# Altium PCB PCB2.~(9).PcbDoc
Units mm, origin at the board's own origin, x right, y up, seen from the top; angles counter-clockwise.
Board outline 79 x 39 mm, 2 copper layers (Top Layer, Bottom Layer); 4 components, 3 nets, 8 pads, 0 vias.
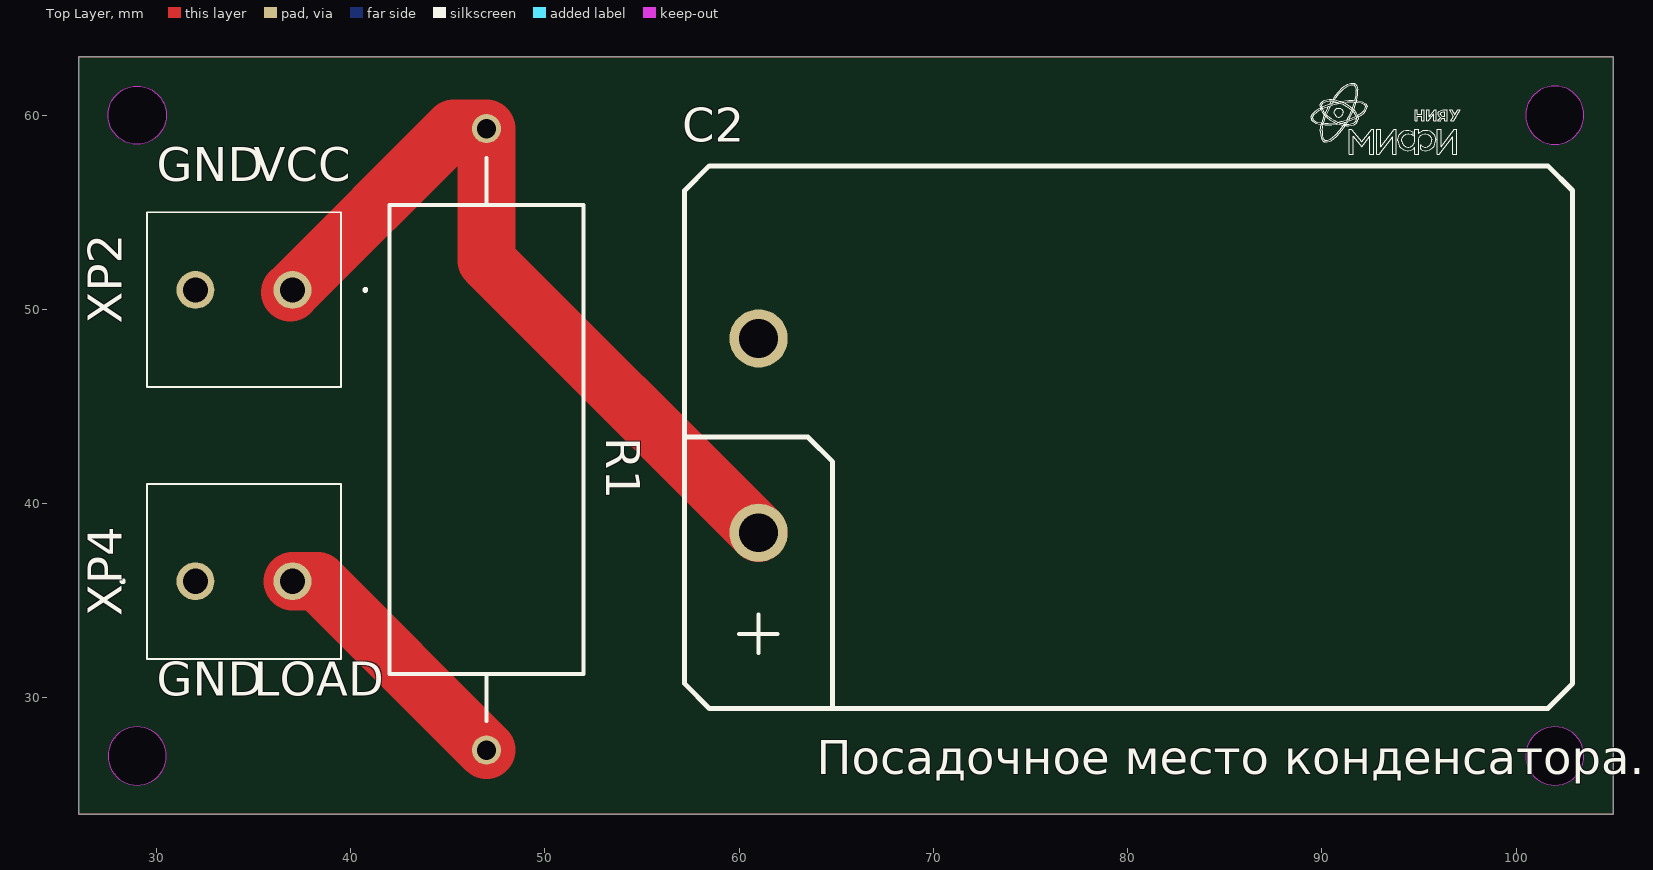
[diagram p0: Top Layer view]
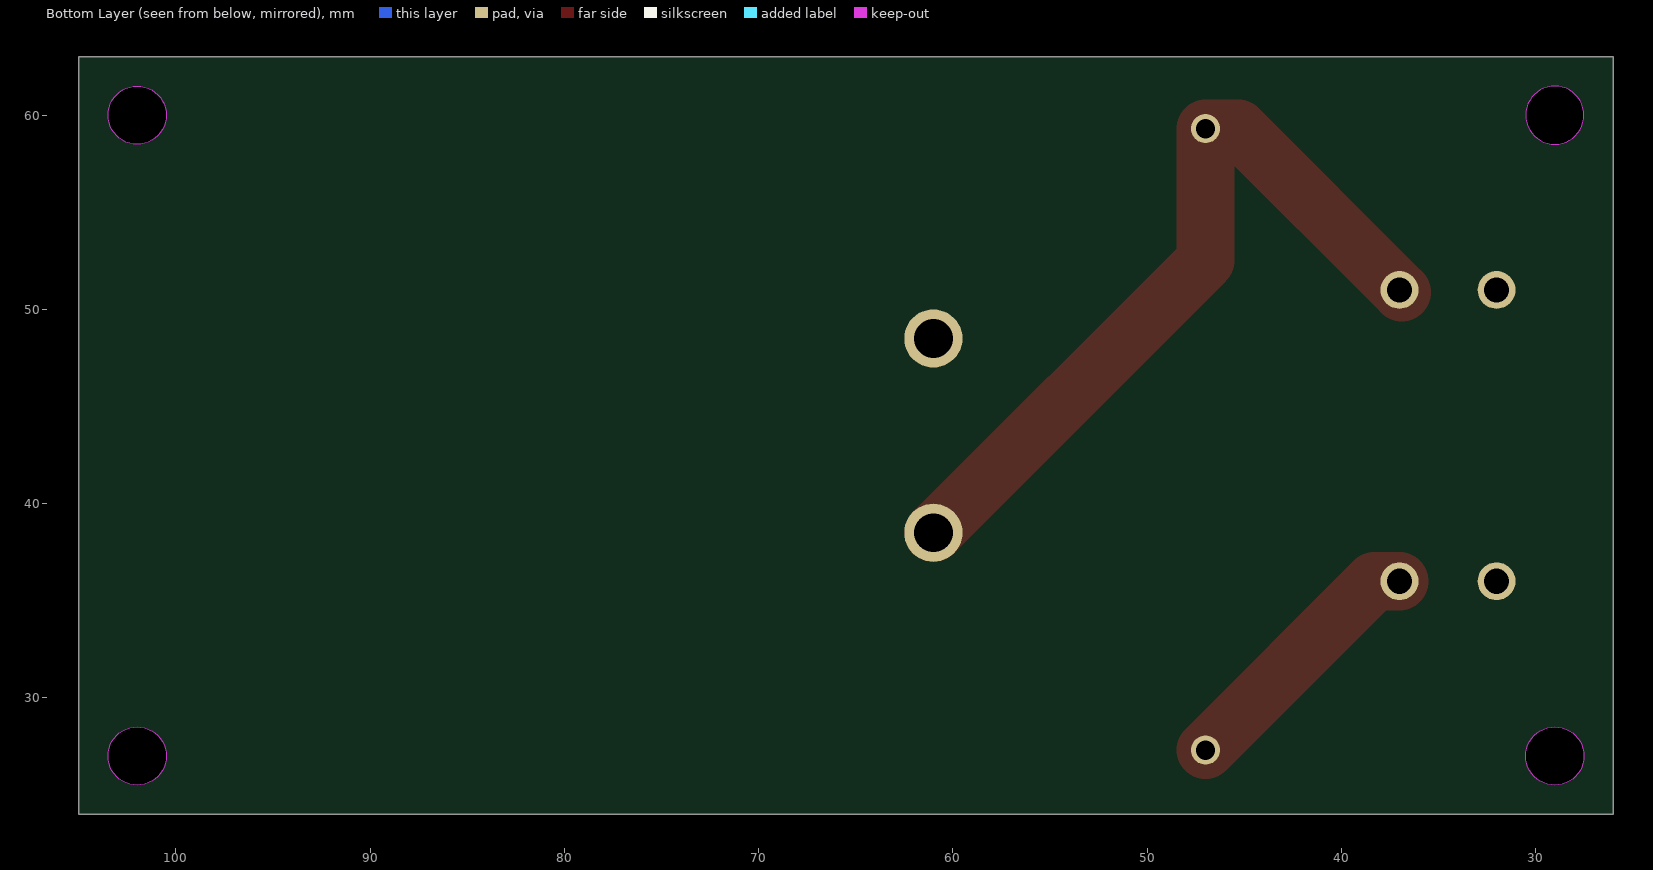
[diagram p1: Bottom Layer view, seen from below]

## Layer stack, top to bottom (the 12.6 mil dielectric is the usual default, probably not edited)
Top Solder: solder mask 0.0102, Solder Resist, Dk 3.5
Top Layer: signal copper 0.0356
Dielectric 1: dielectric 0.32, FR-4, Dk 4.8
Bottom Layer: signal copper 0.0356
Bottom Solder: solder mask 0.0102, Solder Resist, Dk 3.5

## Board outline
26,24 105,24 105,63 26,63
cut-out: 100.5,60 ccw(c102,60) 102,58.5 ccw(c102,60) 103.5,60 ccw(c102,60) 102,61.5 ccw(c102,60)
cut-out: 100.5,27 ccw(c102,27) 102,25.5 ccw(c102,27) 103.5,27 ccw(c102,27) 102,28.5 ccw(c102,27)
cut-out: 27.5,27 ccw(c29,27) 29,25.5 ccw(c29,27) 30.5,27 ccw(c29,27) 29,28.5 ccw(c29,27)
cut-out: 29,58.5 cw(c29,60) 27.5,60 cw(c29,60) 29,61.5 cw(c29,60) 30.5,60 cw(c29,60)

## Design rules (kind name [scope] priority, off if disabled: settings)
Clearance [All] p1: gap=0.254 ignorepadtopadclearanceinfootprint=FALSE except(0: Arc-Hole Track-Hole SMDPad-Hole THPad-Hole Via-Hole Fill-Hole Poly-Hole Region-Hole Text-Hole)
PlaneConnect [All] p1: planeconnectstyle=Relief reliefexpansion=1 reliefentries=4 reliefconductorwidth=3 reliefairgap=0.5
PolygonConnect [All] p1: connectstyle=Relief reliefconductorwidth=1 reliefentries=4 polygonreliefangle="90 Angle" airgapwidth=0.5
RoutingVias [All] p1: holewidth=0.711 width=1.27 viastyle="Through Hole" minholewidth=0.711 minwidth=1.27 maxholewidth=0.711 maxwidth=1.27
SolderMaskExpansion [All] p1: expansion=0.102 istentingtop=FALSE
Width [All] p1: maxlimit=20 minlimit=1 preferedwidth=8
29 further rules are at their usual default settings.

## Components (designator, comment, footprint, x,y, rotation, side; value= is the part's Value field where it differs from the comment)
C2 "1500uF" K50-98-63V-1500uF 61,48.5 r270 top
R1 "2 Ом" "SQP 5W2" 46.99,59.305 r270 top
XP2 "DG300-5.0-02P-12-00A_H_" DG3005002P1200AH 37,51 r180 top
XP4 "DG300-5.0-02P-12-00A_H_" DG3005002P1200AH 32,36 r0 top

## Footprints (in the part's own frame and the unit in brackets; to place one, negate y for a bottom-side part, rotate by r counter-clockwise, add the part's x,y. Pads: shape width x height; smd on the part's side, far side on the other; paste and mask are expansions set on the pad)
DG3005002P1200AH [mm]
  round 1.95 hole 1.3: 1(0,0) 2(5,0)
  silkscreen extent -3.8,-4 7.5,5, body extent -2.46,-4 7.54,5, height 12.6
K50-98-63V-1500uF [mm]
  round 3 hole 2: 1(0,0) 2(10,0)
  silkscreen extent -8.89,-3.81 19.05,41.91, body extent -7.5,10 17.5,40, height 25
"SQP 5W2" [mm]
  round 1.5 hole 1: 1(0,0) 2(32,0)
  silkscreen extent 1.5,-5 30.5,5, body extent -0.35,-5 32.35,5, height 9

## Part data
C2: library part K50-98-63V-1500uF
R1: library part "SQP 5W"
XP2 XP4: "Клеммник винтовой, 2-контактный, 5мм, прямой", Manufacturer_Name=Degson, Manufacturer_Part_Number=DG300-5.0-02P-12-00A(H)

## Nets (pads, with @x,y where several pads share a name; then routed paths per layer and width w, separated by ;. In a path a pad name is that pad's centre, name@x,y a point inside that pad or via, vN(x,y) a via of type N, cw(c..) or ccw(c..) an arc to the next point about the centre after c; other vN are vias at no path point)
GND: C2.1 XP2.2 XP4.1
NetR1_2: R1.2 XP4.2 | length 13.6
  Top Layer w3: XP4.2 38.295,36 R1.2
VCC1: C2.2 R1.1 XP2.1 | length 40.2
  Top Layer w3: XP2.1@36.883,50.883 XP2.1 45.305,59.305 R1.1 46.99,52.51 C2.2

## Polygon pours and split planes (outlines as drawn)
GND on Top Layer "NONET_L01_P000" (solid, shelved, pour order 0): 26,63 105,63 105,24 26,24

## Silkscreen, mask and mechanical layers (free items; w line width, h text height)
Top Overlay:
  drawing of 583 lines, arcs and shapes, not listed
  text "GND" at 30,56 h3
  text "VCC" at 35,56 h3
  text "GND" at 30,29.5 h3
  text "LOAD" at 35,29.5 h3
  text "Посадочное место конденсатора." at 64,25.473 h3
Mechanical 15:
  circle w0.254: c102,60 r1.5
  circle w0.254: c102,27 r1.5
  circle w0.254: c29,27 r1.5
  circle w0.254: c29,60 r1.5
  lines w0.254: 26,24 26,63 105,63 105,24 26,24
